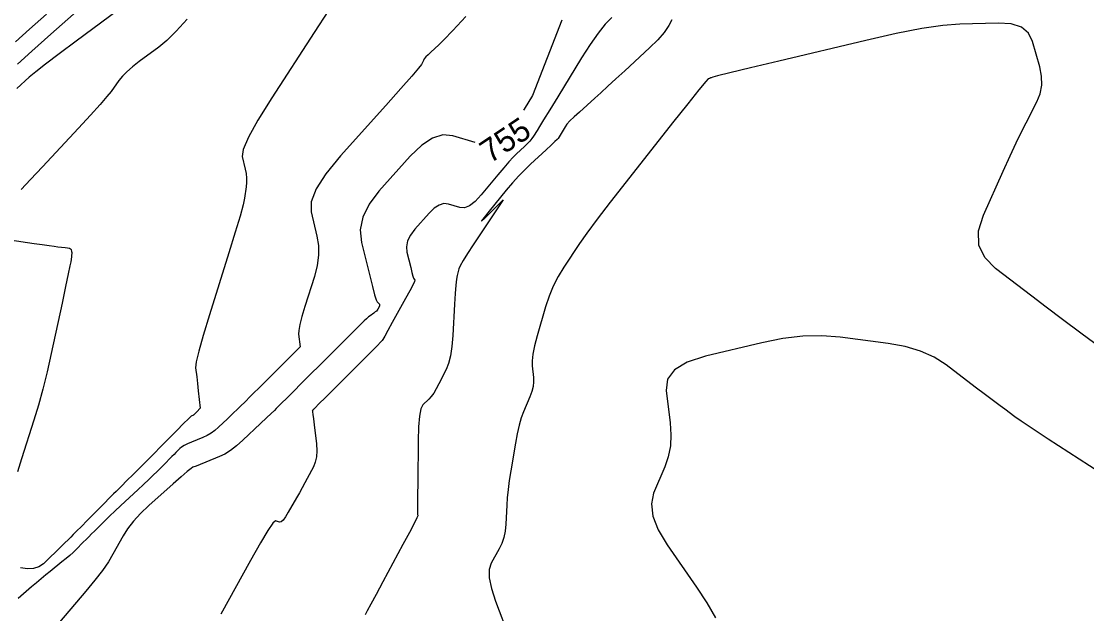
# Model space of a CAD drawing. Extents: x 2079879 to 2092887, y 778083 to 784051.
# Drawn here: x 2084359.8 to 2084488.3, y 780930 to 781001.4 of the extents above; entities that cross this region are included whole.
import ezdxf

# ---------------------------------------------------------------- set-up
doc = ezdxf.new("R2010")
doc.units = 0
doc.layers.add('DT_X_Contour_Major', color=7, linetype='Continuous')
doc.layers.add('DT_X_Contour_Minor', color=7, linetype='Continuous')

msp = doc.modelspace()

# ---------------------------------------------------------------- linework, layer by layer
at = {"layer": 'DT_X_Contour_Major'}
for points in [[(2084382.57, 781017.5), (2084380.83, 781015.83), (2084379, 781014.08), (2084377.63, 781012.77), (2084376.73, 781011.9), (2084376.3, 781011.46), (2084375.76, 781010.89), (2084375.26, 781010.41), (2084374.18, 781009.42), (2084372.5, 781007.92), (2084370.22, 781005.89), (2084363.37, 780999.81), (2084361.08, 780997.77), (2084359.34, 780996.2)], [(2084424.98, 781001.5), (2084421.46, 780992.41), (2084420.45, 780990.77), (2084420.38, 780990.66)], [(2084414.54, 780986.75), (2084411.85, 780987.56), (2084410.66, 780987.66), (2084409.41, 780987.29), (2084408.09, 780986.43), (2084406.71, 780985.09), (2084402.93, 780980.88), (2084401.74, 780979.31), (2084400.99, 780977.76), (2084400.69, 780976.23), (2084400.84, 780974.71), (2084401.83, 780970.7), (2084402.16, 780969.38), (2084402.42, 780968.41), (2084402.61, 780967.8), (2084402.73, 780967.54), (2084402.94, 780967.34), (2084403, 780967.26), (2084403.02, 780967.17), (2084403.02, 780967.07), (2084402.97, 780966.96), (2084402.81, 780966.67), (2084402.73, 780966.56), (2084402.63, 780966.44), (2084402.5, 780966.33), (2084402.34, 780966.2), (2084401.88, 780965.88), (2084401.68, 780965.73), (2084401.44, 780965.52), (2084401.16, 780965.26), (2084400.84, 780964.95), (2084399.93, 780964.03), (2084399.48, 780963.58), (2084398.82, 780962.92), (2084397.94, 780962.05), (2084396.85, 780960.96), (2084393.66, 780957.78), (2084392.59, 780956.71), (2084391.78, 780955.91), (2084391.24, 780955.37), (2084390.96, 780955.09), (2084390.56, 780954.69), (2084390.33, 780954.46), (2084389.93, 780954.09), (2084389.38, 780953.57), (2084388.66, 780952.89), (2084386.53, 780950.9), (2084385.76, 780950.21), (2084385.03, 780949.65), (2084384.36, 780949.21), (2084383.73, 780948.9), (2084380.92, 780947.74), (2084380.51, 780947.62), (2084380.29, 780947.48), (2084379.82, 780947.1), (2084379.1, 780946.47), (2084378.13, 780945.61), (2084375.21, 780942.99), (2084374.19, 780942.03), (2084373.33, 780941.1), (2084372.63, 780940.21), (2084372.09, 780939.36), (2084370.87, 780937.13), (2084370.32, 780936.23), (2084369.59, 780935.19), (2084368.68, 780934), (2084367.59, 780932.68), (2084364.43, 780928.96)]]:
    msp.add_lwpolyline(points, dxfattribs=at)
at = {"layer": 'DT_X_Contour_Minor'}
for points in [[(2084372.45, 781003.42), (2084366.42, 780998.96), (2084364.37, 780997.43), (2084362.75, 780996.2), (2084361.55, 780995.26), (2084360.77, 780994.61), (2084359.26, 780993.27)], [(2084362.86, 781002.24), (2084360.8, 781000.4), (2084359.13, 780998.89)], [(2084396.84, 781002.68), (2084395.14, 781000.03), (2084390.02, 780992.12), (2084388.35, 780989.46), (2084387.2, 780987.39), (2084386.57, 780985.93), (2084386.45, 780985.06), (2084386.81, 780983.56), (2084386.92, 780983), (2084386.98, 780982.46), (2084386.98, 780981.93), (2084386.94, 780981.41), (2084386.74, 780980.05), (2084386.56, 780979.25), (2084386.19, 780977.88), (2084385.62, 780975.95), (2084384.84, 780973.44), (2084382.5, 780966), (2084381.74, 780963.5), (2084381.21, 780961.61), (2084380.91, 780960.31), (2084380.84, 780959.6), (2084380.97, 780958.52), (2084381.01, 780958.11), (2084381.06, 780957.69), (2084381.11, 780957.25), (2084381.16, 780956.81), (2084381.4, 780954.72), (2084380.97, 780954.29), (2084380.89, 780954.21), (2084380.82, 780954.14), (2084380.76, 780954.09), (2084380.72, 780954.05), (2084380.64, 780953.97), (2084380.6, 780953.94), (2084380.57, 780953.91), (2084380.53, 780953.89), (2084380.49, 780953.87), (2084380.38, 780953.83), (2084380.3, 780953.76), (2084380.12, 780953.6), (2084379.86, 780953.34), (2084379.5, 780952.99), (2084378.43, 780951.91), (2084377.96, 780951.44), (2084377.36, 780950.84), (2084376.64, 780950.11), (2084375.78, 780949.25), (2084373.33, 780946.79), (2084372.52, 780945.98), (2084371.94, 780945.39), (2084371.58, 780945.03), (2084371.44, 780944.89), (2084371.37, 780944.83), (2084371.25, 780944.71), (2084370.95, 780944.41), (2084370.46, 780943.92), (2084369.79, 780943.24), (2084367.75, 780941.19), (2084367.06, 780940.49), (2084366.49, 780939.92), (2084366.07, 780939.5), (2084365.78, 780939.21), (2084364.76, 780938.17), (2084362.48, 780935.99), (2084361.94, 780935.61), (2084361.3, 780935.41), (2084360.55, 780935.37), (2084359.71, 780935.51)], [(2084413.43, 781001.93), (2084411.86, 781000.25), (2084410.77, 780999.11), (2084410.17, 780998.51), (2084409.2, 780997.64), (2084408.87, 780997.33), (2084408.6, 780997.06), (2084408.41, 780996.83), (2084408.29, 780996.63), (2084408.06, 780996.16), (2084407.72, 780995.72), (2084406.9, 780994.75), (2084405.58, 780993.25), (2084403.78, 780991.23), (2084398.31, 780985.13), (2084396.55, 780982.99), (2084395.37, 780981.16), (2084394.77, 780979.62), (2084394.75, 780978.38), (2084395.46, 780975.48), (2084395.64, 780974.36), (2084395.65, 780973.17), (2084395.49, 780971.92), (2084395.15, 780970.6), (2084394.02, 780967), (2084393.65, 780965.77), (2084393.4, 780964.81), (2084393.27, 780964.1), (2084393.24, 780963.64), (2084393.42, 780962.12), (2084389.29, 780958), (2084388.48, 780957.19), (2084387.81, 780956.53), (2084387.29, 780956.01), (2084386.92, 780955.64), (2084386.12, 780954.85), (2084385.81, 780954.54), (2084385.46, 780954.2), (2084385.09, 780953.85), (2084384.69, 780953.47), (2084383.58, 780952.43), (2084383.16, 780952.06), (2084382.7, 780951.74), (2084382.22, 780951.46), (2084381.71, 780951.22), (2084380.32, 780950.65), (2084379.85, 780950.44), (2084379.45, 780950.24), (2084379.15, 780950.04), (2084378.92, 780949.86), (2084378.45, 780949.38), (2084378.24, 780949.17), (2084377.97, 780948.91), (2084377.65, 780948.58), (2084377.27, 780948.2), (2084376.18, 780947.11), (2084375.73, 780946.66), (2084375.19, 780946.14), (2084374.56, 780945.55), (2084373.85, 780944.88), (2084371.82, 780943), (2084371.1, 780942.34), (2084370.5, 780941.76), (2084369.99, 780941.28), (2084369.59, 780940.88), (2084368.65, 780939.93), (2084368.3, 780939.58), (2084367.96, 780939.24), (2084367.62, 780938.9), (2084367.29, 780938.57), (2084366.43, 780937.7), (2084366.08, 780937.36), (2084365.68, 780937), (2084365.22, 780936.61), (2084364.72, 780936.2), (2084363.31, 780935.07), (2084362.78, 780934.64), (2084362.22, 780934.18), (2084361.65, 780933.7), (2084361.05, 780933.19), (2084359.45, 780931.81)], [(2084379.82, 781001.61), (2084378.49, 781000.17), (2084377.35, 780999.04), (2084376.38, 780998.23), (2084374.04, 780996.5), (2084373.23, 780995.87), (2084372.55, 780995.29), (2084372, 780994.74), (2084371.59, 780994.23), (2084370.66, 780992.92), (2084370.15, 780992.28), (2084369.32, 780991.32), (2084368.17, 780990.05), (2084366.71, 780988.47), (2084362.37, 780983.83), (2084360.92, 780982.28), (2084359.8, 780981.08)], [(2084431.02, 781001.81), (2084430.23, 781001), (2084429.36, 780999.93), (2084428.41, 780998.58), (2084427.37, 780996.96), (2084424.49, 780992.27), (2084423.53, 780990.7), (2084422.79, 780989.5), (2084422.28, 780988.67), (2084422, 780988.22), (2084421.56, 780987.5), (2084421.37, 780987.23), (2084421.13, 780986.93), (2084420.84, 780986.62), (2084420.5, 780986.29), (2084419.53, 780985.38), (2084419.11, 780984.97), (2084418.6, 780984.42), (2084417.99, 780983.72), (2084417.28, 780982.87), (2084415.27, 780980.43), (2084414.54, 780979.65), (2084413.87, 780979.14), (2084413.26, 780978.89), (2084412.7, 780978.92), (2084411.31, 780979.34), (2084410.77, 780979.39), (2084410.2, 780979.22), (2084409.6, 780978.83), (2084408.98, 780978.22), (2084407.27, 780976.31), (2084406.73, 780975.6), (2084406.39, 780974.9), (2084406.25, 780974.2), (2084406.32, 780973.52), (2084406.77, 780971.7), (2084406.92, 780971.1), (2084407.04, 780970.66), (2084407.12, 780970.39), (2084407.17, 780970.27), (2084407.27, 780970.18), (2084407.23, 780970.01), (2084407.02, 780969.58), (2084406.66, 780968.89), (2084406.14, 780967.94), (2084404.54, 780965.05), (2084404.02, 780964.1), (2084403.64, 780963.42), (2084403.42, 780963.01), (2084403.34, 780962.88), (2084403.34, 780962.88), (2084403.18, 780962.72), (2084402.72, 780962.26), (2084401.95, 780961.48), (2084400.87, 780960.4), (2084397.57, 780957.11), (2084396.49, 780956.02), (2084395.71, 780955.25), (2084395.24, 780954.77), (2084395.07, 780954.61), (2084395.03, 780954.57), (2084395.02, 780954.56), (2084395.01, 780954.55), (2084395, 780954.54), (2084395, 780954.54), (2084394.99, 780954.53), (2084394.99, 780954.53), (2084394.98, 780954.52), (2084394.97, 780954.51), (2084394.95, 780954.49), (2084394.87, 780954.41), (2084394.91, 780954.42), (2084394.93, 780954.31), (2084394.97, 780953.99), (2084395.04, 780953.46), (2084395.13, 780952.71), (2084395.39, 780950.42), (2084395.44, 780949.61), (2084395.4, 780948.88), (2084395.26, 780948.23), (2084395.03, 780947.66), (2084394.28, 780946.26), (2084393.99, 780945.73), (2084393.67, 780945.15), (2084393.34, 780944.55), (2084392.98, 780943.92), (2084392.01, 780942.19), (2084391.67, 780941.63), (2084391.38, 780941.24), (2084391.13, 780941.03), (2084390.94, 780941), (2084390.48, 780941.14), (2084390.16, 780940.88), (2084389.55, 780940.01), (2084388.65, 780938.51), (2084387.45, 780936.39), (2084383.88, 780929.92)], [(2084438.24, 781001.55), (2084437.9, 781000.84), (2084437.34, 781000.03), (2084436.56, 780999.14), (2084435.55, 780998.15), (2084432.57, 780995.4), (2084431.51, 780994.42), (2084430.55, 780993.54), (2084429.7, 780992.76), (2084428.95, 780992.09), (2084427.1, 780990.42), (2084426.47, 780989.84), (2084425.97, 780989.35), (2084425.61, 780988.96), (2084425.39, 780988.65), (2084424.53, 780987.25), (2084424.42, 780987.13), (2084424.14, 780986.87), (2084423.7, 780986.45), (2084423.09, 780985.88), (2084421.23, 780984.16), (2084420.53, 780983.48), (2084419.8, 780982.72), (2084419.06, 780981.89), (2084418.29, 780980.99), (2084416.23, 780978.49), (2084415.61, 780977.73), (2084415.31, 780977.33), (2084415.32, 780977.28), (2084415.65, 780977.58), (2084417.91, 780979.83), (2084414.3, 780974.42), (2084413.61, 780973.37), (2084413.1, 780972.53), (2084412.75, 780971.91), (2084412.58, 780971.51), (2084412.36, 780970.72), (2084412.27, 780970.28), (2084412.19, 780969.56), (2084412.11, 780968.56), (2084412.04, 780967.28), (2084411.83, 780963.5), (2084411.73, 780962.18), (2084411.56, 780961.05), (2084411.33, 780960.12), (2084411.03, 780959.38), (2084410.16, 780957.66), (2084409.85, 780957.06), (2084409.54, 780956.56), (2084409.25, 780956.15), (2084408.97, 780955.84), (2084408.24, 780955.12), (2084408, 780954.65), (2084407.83, 780953.77), (2084407.71, 780952.5), (2084407.66, 780950.82), (2084407.61, 780945.82), (2084407.6, 780944.17), (2084407.59, 780942.98), (2084407.59, 780942.23), (2084407.59, 780941.95), (2084407.61, 780941.78), (2084407.5, 780941.52), (2084407.17, 780940.85), (2084406.61, 780939.77), (2084405.81, 780938.29), (2084403.4, 780933.79), (2084402.59, 780932.28), (2084401.96, 780931.12), (2084401.52, 780930.3), (2084401.26, 780929.84)], [(2084490, 780961.98), (2084487.57, 780963.79), (2084485.37, 780965.44), (2084483.39, 780966.92), (2084481.64, 780968.24), (2084477.29, 780971.55), (2084475.97, 780972.89), (2084475.28, 780974.4), (2084475.23, 780976.11), (2084475.81, 780978), (2084478.19, 780983.28), (2084479.03, 780985.13), (2084479.77, 780986.72), (2084480.42, 780988.06), (2084480.96, 780989.13), (2084482.27, 780991.66), (2084482.66, 780992.63), (2084482.85, 780993.65), (2084482.83, 780994.73), (2084482.61, 780995.86), (2084481.75, 780998.94), (2084481.25, 780999.94), (2084480.39, 781000.65), (2084479.18, 781001.05), (2084477.61, 781001.15), (2084472.96, 781001.02), (2084470.94, 781000.86), (2084468.38, 781000.48), (2084465.28, 780999.88), (2084461.63, 780999.06), (2084451.17, 780996.57), (2084447.73, 780995.75), (2084445.26, 780995.16), (2084443.74, 780994.79), (2084443.19, 780994.64), (2084442.99, 780994.56), (2084442.92, 780994.53), (2084442.86, 780994.5), (2084442.8, 780994.48), (2084442.75, 780994.47), (2084442.63, 780994.44), (2084442.33, 780994.1), (2084441.51, 780993.1), (2084440.18, 780991.43), (2084438.34, 780989.11), (2084432.74, 780982.02), (2084430.81, 780979.57), (2084429.23, 780977.5), (2084428, 780975.84), (2084427.11, 780974.57), (2084425.21, 780971.72), (2084424.54, 780970.62), (2084423.95, 780969.46), (2084423.45, 780968.24), (2084423.03, 780966.96), (2084422.03, 780963.47), (2084421.71, 780962.26), (2084421.5, 780961.25), (2084421.4, 780960.43), (2084421.4, 780959.82), (2084421.57, 780958.45), (2084421.59, 780957.92), (2084421.52, 780957.35), (2084421.37, 780956.74), (2084421.13, 780956.09), (2084420.37, 780954.31), (2084420.1, 780953.57), (2084419.84, 780952.69), (2084419.61, 780951.66), (2084419.39, 780950.5), (2084418.83, 780947.2), (2084418.64, 780946.01), (2084418.5, 780944.92), (2084418.39, 780943.93), (2084418.34, 780943.03), (2084418.24, 780940.76), (2084418.16, 780939.93), (2084418, 780939.16), (2084417.76, 780938.44), (2084417.44, 780937.77), (2084416.47, 780936.06), (2084416.23, 780935.29), (2084416.23, 780934.27), (2084416.49, 780933.01), (2084416.99, 780931.49), (2084418.65, 780927.12)], [(2084358.42, 780975.04), (2084361.35, 780974.6), (2084362.35, 780974.45), (2084363.17, 780974.33), (2084363.79, 780974.25), (2084364.22, 780974.2), (2084365.11, 780974.1), (2084365.4, 780974.06), (2084365.62, 780974), (2084365.76, 780973.93), (2084365.82, 780973.85), (2084365.88, 780973.61), (2084365.89, 780973.51), (2084365.89, 780973.37), (2084365.88, 780973.19), (2084365.86, 780972.98), (2084365.77, 780972.39), (2084365.68, 780971.9), (2084365.48, 780970.91), (2084365.16, 780969.41), (2084364.73, 780967.39), (2084363.43, 780961.32), (2084362.93, 780959.11), (2084362.42, 780957.03), (2084361.89, 780955.09), (2084361.34, 780953.28), (2084359.86, 780948.63), (2084359.34, 780947.05)], [(2084493.6, 780944.57), (2084486.13, 780949.4), (2084483.62, 780951.02), (2084481.7, 780952.28), (2084480.36, 780953.17), (2084479.61, 780953.69), (2084478.39, 780954.6), (2084477.83, 780955.02), (2084477.05, 780955.61), (2084476.05, 780956.36), (2084474.84, 780957.28), (2084471.32, 780959.95), (2084469.89, 780960.87), (2084468.25, 780961.6), (2084466.4, 780962.15), (2084464.34, 780962.53), (2084458.56, 780963.28), (2084456.34, 780963.46), (2084454.03, 780963.4), (2084451.62, 780963.13), (2084449.12, 780962.63), (2084442.32, 780961.01), (2084440.11, 780960.3), (2084438.59, 780959.37), (2084437.74, 780958.23), (2084437.58, 780956.87), (2084438.06, 780952.97), (2084438.15, 780951.54), (2084438.07, 780950.18), (2084437.82, 780948.89), (2084437.4, 780947.66), (2084436.06, 780944.48), (2084435.78, 780943.2), (2084435.96, 780941.74), (2084436.6, 780940.09), (2084437.7, 780938.26), (2084441.23, 780933.15), (2084442.46, 780931.27), (2084443.53, 780929.46)]]:
    msp.add_lwpolyline(points, dxfattribs=at)

# ---------------------------------------------------------------- texts
at = {"layer": 'DT_X_Contour_Major'}
msp.add_text('755', height=2.8, rotation=33.7475, dxfattribs=at).set_placement((2084416.33, 780984.16))

doc.saveas('drawing.dxf')
